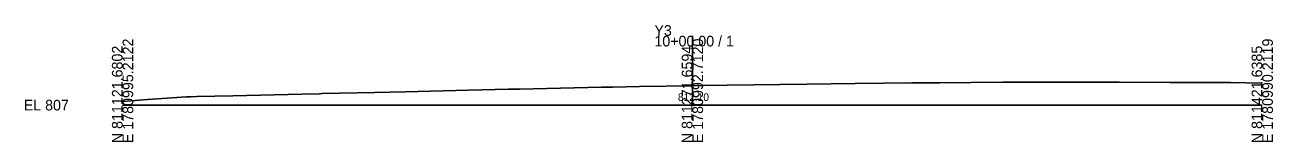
# Model space of a CAD drawing. Extents: x -26 to 303, y -10 to 4017.
# Drawn here: x -25.7 to 302.8, y -9.7 to 21.1 of the extents above; entities that cross this region are included whole.
import ezdxf

# ---------------------------------------------------------------- set-up
doc = ezdxf.new("R2010")
doc.units = 0
for name, color, linetype in [('Exist Cross Section Cell', 7, 'Continuous'), ('Exist XS Center Line Elevation Label', 7, 'Continuous'), ('Exist XS Ground Line', 7, 'Continuous')]:
    doc.layers.add(name, color=color, linetype=linetype)

msp = doc.modelspace()

# ---------------------------------------------------------------- linework, layer by layer
at = {"layer": 'Exist Cross Section Cell'}
for p, q in [((150, 0), (150, 18.21)), ((0, 0), (150, 0)), ((150, 0), (300, 0))]:
    msp.add_line(p, q, dxfattribs=at)
at = {"layer": 'Exist XS Ground Line'}
for p, q in [((52.56, 3.01), (66.3, 3.35)), ((66.3, 3.35), (74.4, 3.53)), ((74.4, 3.53), (91.04, 3.93)), ((91.04, 3.93), (101.58, 4.17)), ((101.58, 4.17), (102.37, 4.18)), ((102.37, 4.18), (103.12, 4.2)), ((103.12, 4.2), (103.6, 4.21)), ((103.6, 4.21), (104.01, 4.22)), ((104.01, 4.22), (104.47, 4.23)), ((104.47, 4.23), (126.05, 4.68)), ((126.05, 4.68), (126.85, 4.7)), ((126.85, 4.7), (128.95, 4.75)), ((128.95, 4.75), (136.06, 4.89)), ((136.06, 4.89), (150, 5.1)), ((150, 5.1), (152.8, 5.14)), ((152.8, 5.14), (159.17, 5.22)), ((159.17, 5.22), (180.12, 5.5)), ((180.12, 5.5), (192.82, 5.64)), ((192.82, 5.64), (207.74, 5.82)), ((207.74, 5.82), (215.1, 5.88)), ((215.1, 5.88), (231.61, 6.04)), ((231.61, 6.04), (235.57, 6.04)), ((235.57, 6.04), (255.4, 6.07)), ((255.4, 6.07), (262.3, 6.04)), ((262.3, 6.04), (275.8, 5.97)), ((275.8, 5.97), (284.86, 5.93)), ((284.86, 5.93), (291.67, 5.9)), ((291.67, 5.9), (300, 5.78)), ((0, 0.95), (6.54, 1.51)), ((6.54, 1.51), (16.81, 2.14)), ((16.81, 2.14), (17.95, 2.2)), ((17.95, 2.2), (19.59, 2.29)), ((19.59, 2.29), (29.04, 2.44)), ((29.04, 2.44), (47.23, 2.89)), ((47.23, 2.89), (51.74, 3)), ((51.74, 3), (52.56, 3.01))]:
    msp.add_line(p, q, dxfattribs=at)

# ---------------------------------------------------------------- texts
at = {"layer": 'Exist Cross Section Cell'}
for s, p in [('Y3', (140, 18.21)), ('10+00.00 / 1', (140, 15.41)), ('EL 807', (-26, -1.4))]:
    msp.add_text(s, height=2.8, dxfattribs=at).set_placement(p)
for s, p in [('E 1780995.2122', (2.8, -10)), ('E 1780992.7120', (152.8, -10)), ('E 1780990.2119', (302.8, -10)), ('N 811121.6802', (0, -10)), ('N 811271.6594', (150, -10)), ('N 811421.6385', (300, -10))]:
    msp.add_text(s, height=2.8, rotation=90, dxfattribs=at).set_placement(p)
at = {"layer": 'Exist XS Center Line Elevation Label'}
msp.add_text('812.10', height=2, dxfattribs=at).set_placement((146.19, 1.1))

doc.saveas('drawing.dxf')
